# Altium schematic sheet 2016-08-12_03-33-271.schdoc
size 313 x 134 mm; SheetNumber: 1; SheetTotal: 1
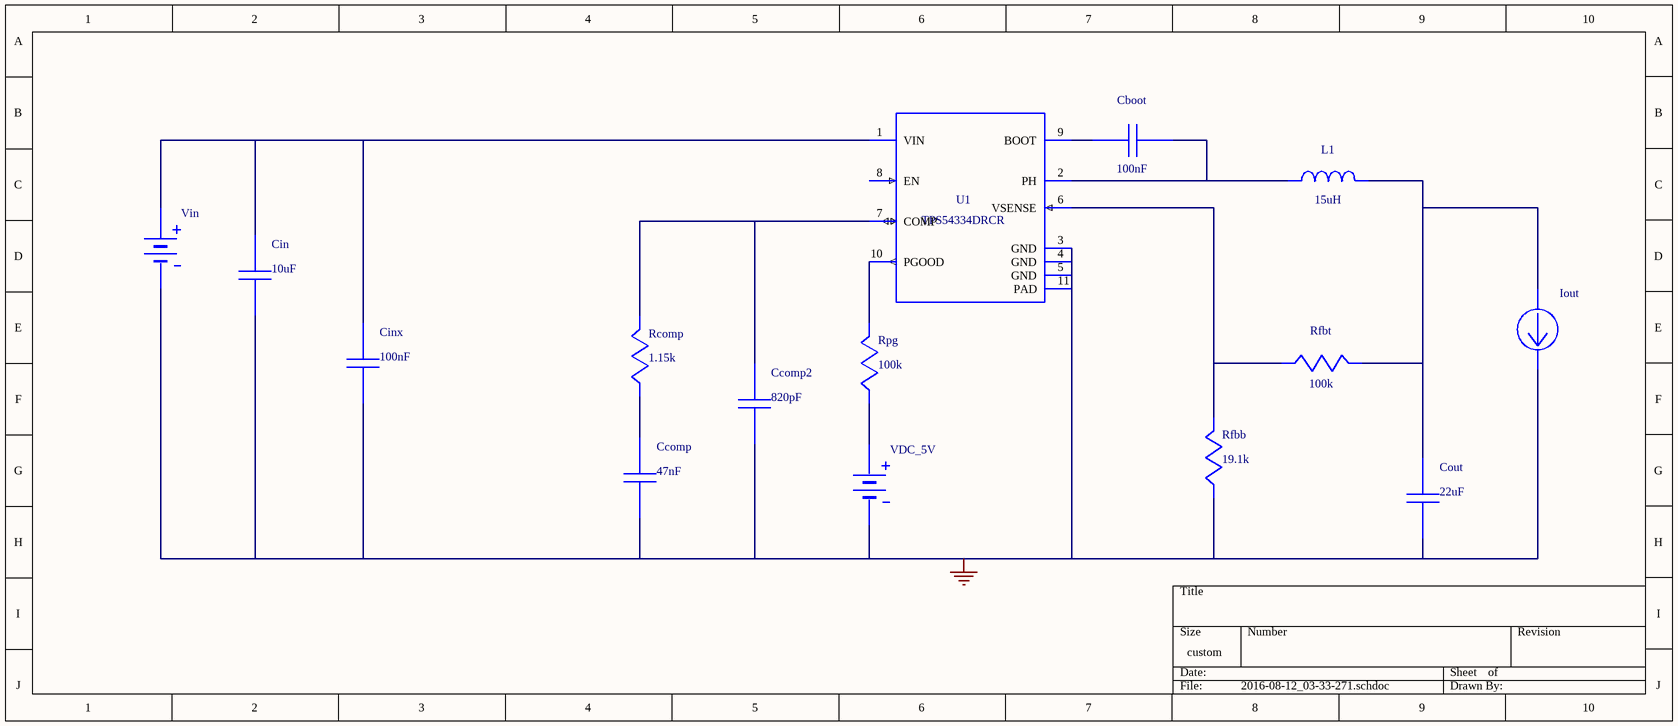
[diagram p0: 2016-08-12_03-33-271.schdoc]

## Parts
Cboot  value 100nF  (hidden comment: C0805C104K5RACTU)
Ccomp  value 47nF  (hidden comment: TMK212B7473KD-T)
Ccomp2  value 820pF  (hidden comment: CC0805KRX7R9BB821)
Cin  value 10uF  (hidden comment: GRM219R61A106KE44D)
Cinx  value 100nF  (hidden comment: C0805C104K5RACTU)
Cout  value 22uF  (hidden comment: GRM31CR61A226KE19L)
Iout  WB_CURRENT_LOAD  (value not drawn)
L1  value 15uH  (hidden comment: SRN6045-150M)
Rcomp  value 1.15k  (hidden comment: CRCW04021K15FKED)
Rfbb  value 19.1k  (hidden comment: CRCW040219K1FKED)
Rfbt  value 100k  (hidden comment: CRCW0402100KFKED)
Rpg  value 100k  (hidden comment: CRCW0402100KFKED)
U1  TPS54334DRCR
VDC_5V  WB_PRIM_DC_VOLTAGE_SOURCE  (value not drawn)
Vin  WB_BATTERY  (value not drawn)

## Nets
0: Ccomp.2 Ccomp2.2 Cin.2 Cinx.2 Cout.2 Iout.2(-) Rfbb.2 U1.3(GND) U1.4(GND) U1.5(GND) U1.11(PAD) VDC_5V.2(-) Vin.2(-)
NetCboot_1: Cboot.1 U1.9(BOOT)
NetCboot_2: Cboot.2 L1.1 U1.2(PH)
NetCcomp2_1: Ccomp2.1 Rcomp.1 U1.7(COMP)
NetCcomp_1: Ccomp.1 Rcomp.2
NetCin_1: Cin.1 Cinx.1 U1.1(VIN) Vin.1(+)
NetCout_1: Cout.1 Iout.1(+) L1.2 Rfbt.1
NetRfbb_1: Rfbb.1 Rfbt.2 U1.6(VSENSE)
NetRpg_1: Rpg.1 U1.10(PGOOD)
NetRpg_2: Rpg.2 VDC_5V.1(+)

Not connected (* = marked no-connect by the designer): U1 8(EN)

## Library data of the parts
Cboot Cinx = C0805C104K5RACTU: Manufacturer Name: Kemet
Ccomp = TMK212B7473KD-T: Manufacturer Name: Taiyo Yuden
Ccomp2 = CC0805KRX7R9BB821: CC0805KRX7R9BB82; Manufacturer Name: Yageo America
Cin = GRM219R61A106KE44D: GRM219R61A106KE4; Manufacturer Name: MuRata
Cout = GRM31CR61A226KE19L: GRM31CR61A226KE1; Manufacturer Name: MuRata
L1 = SRN6045-150M: Manufacturer Name: Bourns
Rcomp = CRCW04021K15FKED: Manufacturer Name: Vishay-Dale
Rfbb = CRCW040219K1FKED: Manufacturer Name: Vishay-Dale
Rfbt Rpg = CRCW0402100KFKED: Manufacturer Name: Vishay-Dale
U1 = TPS54334DRCR: Manufacturer Name: Texas Instruments
VDC_5V = WB_PRIM_DC_VOLTAGE_SOURCE: WB_PRIM_DC_VOLTA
